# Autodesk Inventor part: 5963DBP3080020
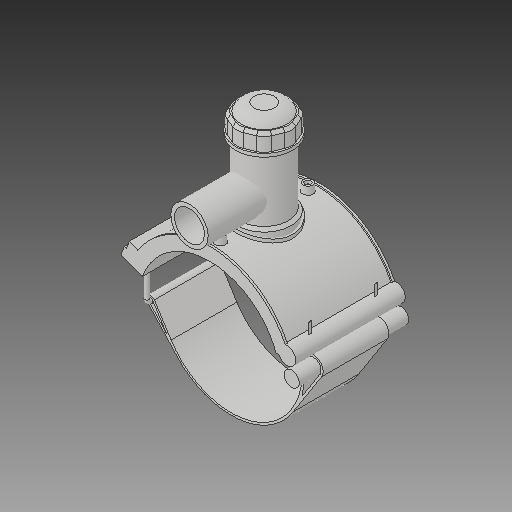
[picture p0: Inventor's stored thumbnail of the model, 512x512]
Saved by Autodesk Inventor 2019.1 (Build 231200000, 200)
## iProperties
Created: 2017-07
Part Number: 5963DBP3080020
Material: Generic
Description: PLASSON TAPPING SADDLE 8''DIPS x 2''IPS
Document SubType Name: Modeling
Designer: KIM
Density: 1 g/cm^3
Appearance: Default
Author: KIM
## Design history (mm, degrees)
derived "5963DBP_5963BUP.ipt"
feature "Solid1::5963DBP_5963BUP.ipt"
feature "Solid2::5963DBP_5963BUP.ipt"
feature "Solid3::5963DBP_5963BUP.ipt"
tag "TaggingFeature1"
body "Solid1"
body "Solid2"
body "Solid3"
other parameters: "d_" = 228.9, "B_" = 179.832, "L_" = 176.022, "d_t" = 6, "H_2" = 177.038, "H_1" = 65.024, "d_1" = 60.1, "H_" = 119.888, "d1" = 265.524, "d148" = 3.4335, "d160" = 3.4335, "d169" = 3.4335, "d192" = 7.3248, "d0" = 228.9, "d2" = 269.748, "d3" = 57.225, "d4" = 176.022, "d5" = 0, "d6" = 0.1, "d8" = 0, "d19" = 6, "d20" = 6, "d21" = 105.6132, "d23" = 0, "d24" = 52.8066, "d26" = 0, "d27" = 3, "d28" = 3, "d29" = 3, "d30" = 76.3, "d31" = 6, "d32" = 0, "d33" = 0, "d34" = 0.6, "d40" = 138.07248, "d41" = 91.56, "d43" = 0, "d45" = 0, "d47" = 238.3752, "d70" = 15, "d72" = 0, "d73" = 6, "d75" = 5, "d76" = 0, "d77" = 11.445, "d78" = 144.45, "d79" = 15, "d80" = 70.4088, "d82" = 5 deg, "d84" = 4, "d85" = 14, "d86" = 0, "d87" = 3, "d88" = 0, "d89" = 1, "d90" = 1, "d91" = 140.8176, "d92" = 0, "d93" = 0.5, "d94" = 120.47368, "d96" = 270.83448, "d97" = 3.52044, "d98" = 0, "d120" = 140 deg, "d121" = 24.228, "d122" = 20 deg, "d123" = 531.048, "d124" = 159.3144, "d126" = 0, "d143" = 235.767, "d145" = 28.17231, "d149" = 3.4335, "d150" = 30.98954, "d153" = 176.022, "d154" = 0, "d156" = 132.762, "d157" = 160 deg, "d159" = 7.3248, "d161" = 3.4335, "d162" = 105.6132, "d163" = 0, "d164" = 114.45, "d167" = 22.89, "d168" = 129.5239, "d170" = 3.4335, "d172" = 0, "d173" = 1, "d175" = 114.45, "d176" = 20 deg, "d177" = 16.023, "d178" = 36.624, "d180" = 0, "d183" = 14.6496, "d184" = 12.8184, "d185" = 57.20715, "d186" = 57.20715, "d187" = 132.762, "d188" = 10.9872, "d189" = 16.023, "d190" = 0, "d191" = 199.143, "d193" = 7.3248, "d194" = 6.16077, "d195" = 90 deg, "d197" = 0, "d199" = 0, "d200" = 18.312, "d202" = 0, "d203" = 177.038, "d204" = 86.982, "d205" = 64.092, "d206" = 77.826, "d207" = 132.7785, "d208" = 138.08964, "d209" = 164.64534, "d210" = 78.7416, "d211" = 91.56, "d212" = 73.248, "d213" = 31.4766, "d216" = 0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
